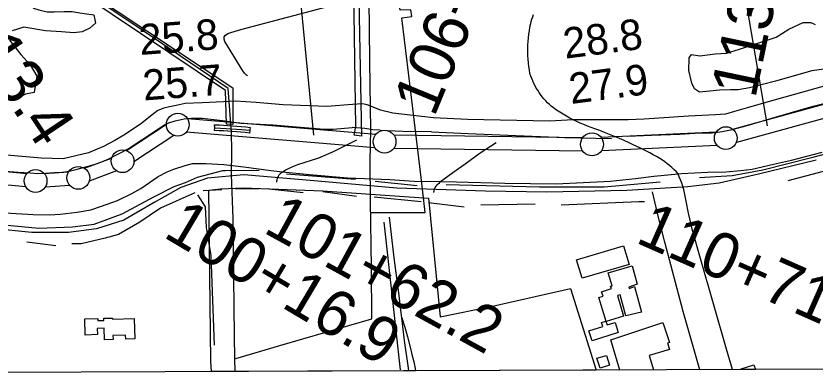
# Model space of a CAD drawing. Extents: x 3392644 to 3430565, y 576657 to 602123.
# Drawn here: x 3398435 to 3400187, y 582044 to 582831 of the extents above; entities that cross this region are included whole.
import ezdxf

# ---------------------------------------------------------------- set-up
doc = ezdxf.new("R2010")
doc.units = 0
for name, color, linetype in [('V-BLDG-OTLN', 7, 'Continuous'), ('V-BRDG-OTLN', 7, 'Continuous'), ('V-CHAN-DOCK', 7, 'Continuous'), ('V-FLOD-BASE', 7, 'Continuous'), ('V-GRID-FRAM', 7, 'Continuous'), ('V-LEVE-TOET', 7, 'Continuous'), ('V-RAIL-TRAK', 7, 'Continuous'), ('V-RIVR-RANG', 7, 'Continuous'), ('V-ROAD-CNTR', 7, 'Continuous'), ('V-SITE-OTLN', 7, 'Continuous'), ('V-SITE-VEGE', 7, 'Continuous'), ('V-SURV-IDEN', 7, 'Continuous'), ('V-SURV-LINE', 7, 'Continuous'), ('V-TOPO-MAJR', 7, 'Continuous'), ('V-TOPO-SHOR', 7, 'Continuous'), ('V-UTIL-LINE', 7, 'Continuous'), ('V-WETL-SWMP', 7, 'Continuous')]:
    doc.layers.add(name, color=color, linetype=linetype)

msp = doc.modelspace()

# ---------------------------------------------------------------- linework, layer by layer
at = {"layer": 'V-BLDG-OTLN'}
for p, q in [((3399739.4, 582121.7), (3399853.2, 582159.3)), ((3399853.2, 582159.3), (3399867.6, 582115.6)), ((3399759, 582055.2), (3399739.4, 582121.7)), ((3399867.6, 582115.6), (3399863.1, 582114.1)), ((3399863.1, 582114.1), (3399868, 582100.4)), ((3399868, 582100.4), (3399823.3, 582087.1)), ((3399823.3, 582087.1), (3399832.8, 582055.4)), ((3400024.7, 582058), (3400052.8, 582066.9)), ((3400052.8, 582066.9), (3400056, 582056.2)), ((3399832.8, 582055.4), (3399759, 582055.2)), ((3400025.3, 582056.1), (3400024.7, 582058)), ((3400056, 582056.2), (3400025.3, 582056.1))]:
    msp.add_line(p, q, dxfattribs=at)
for points in [[(3399779.1, 582286.8), (3399675.9, 582256.3), (3399663.9, 582296.9), (3399766.6, 582327.3)], [(3399766.5, 582173.4), (3399729.2, 582161.7), (3399712.6, 582214.4), (3399721.9, 582217.3), (3399718.9, 582226.8), (3399740.5, 582233.6), (3399738.7, 582239), (3399742.1, 582240), (3399733.2, 582268.4), (3399785.7, 582283.3), (3399797.1, 582243.6), (3399778.3, 582237), (3399779.3, 582234), (3399790.8, 582238.1), (3399806.1, 582182.4), (3399772.3, 582174.2), (3399759.4, 582220.1), (3399753.4, 582218.4)], [(3398585.8, 582167.3), (3398614.1, 582168.3), (3398614.3, 582163.5), (3398627.5, 582163.9), (3398627.4, 582168.6), (3398646, 582169.2), (3398646.1, 582166.6), (3398693.8, 582168.1), (3398695.1, 582123.6), (3398675.3, 582123), (3398675, 582131.8), (3398647.3, 582131), (3398647.6, 582122.1), (3398629.1, 582121.5), (3398628.1, 582147.2), (3398612.9, 582146.6), (3398613.5, 582132.9), (3398586.7, 582131.3)], [(3399755.5, 582137.3), (3399698.2, 582118.9), (3399691.1, 582140.9), (3399721.4, 582150.6), (3399718.5, 582159.6), (3399728.4, 582162.1), (3399730.8, 582154.2), (3399748.9, 582159.7)], [(3399708.7, 582080.9), (3399729.9, 582087.1), (3399736.3, 582065.7), (3399715.4, 582059.5)]]:
    msp.add_lwpolyline(points, close=True, dxfattribs=at)
at = {"layer": 'V-BRDG-OTLN'}
msp.add_lwpolyline([(3398947, 582574.6), (3398937.4, 582575.5), (3398927.8, 582576.4), (3398918.3, 582577.2), (3398908.7, 582577.9), (3398899.1, 582578.6), (3398889.5, 582579.2), (3398879.9, 582579.8), (3398870.3, 582580.3), (3398870.5, 582585.8), (3398870.3, 582592.9), (3398880, 582592.4), (3398889.7, 582591.8), (3398899.5, 582591.1), (3398909.2, 582590.4), (3398918.9, 582589.6), (3398928.7, 582588.8), (3398938.4, 582587.9), (3398948, 582587), (3398948.1, 582586.9), (3398947.5, 582580.6)], close=True, dxfattribs=at)
msp.add_lwpolyline([(3398870.5, 582585.8), (3398895.4, 582584.4), (3398929.7, 582582.7), (3398947.5, 582580.6)], dxfattribs=at)
at = {"layer": 'V-CHAN-DOCK'}
msp.add_lwpolyline([(3398536.3, 583167.9), (3398504.7, 583164), (3398520, 583026.8), (3398526.8, 583027.6), (3398530.3, 583006.9), (3398520.8, 583004.5), (3398533.1, 582924.5), (3398910, 582673.5), (3398910.3, 582593.5), (3398896.4, 582593.9), (3398894, 582667.5), (3398521.5, 582918.1), (3398511.6, 583003.7), (3398504.1, 583002.9), (3398501.3, 583024), (3398508, 583025.2), (3398490.5, 583162.2), (3398455.2, 583157.9), (3398449.8, 583202), (3398530.5, 583211.9)], close=True, dxfattribs=at)
msp.add_lwpolyline([(3399240.3, 583164.2), (3399248.5, 583103), (3399242.2, 583102.2), (3399221.8, 583099.6), (3399217.6, 583133.5), (3399181.5, 583128.9), (3399192.2, 582567.6), (3399176.6, 582569.7), (3399179.6, 582589.2), (3399172.2, 583132.7), (3399148.3, 583130.5), (3399150.6, 583110.2), (3399105.9, 583105), (3399100.8, 583147.8)], dxfattribs=at)
at = {"layer": 'V-FLOD-BASE'}
for p in [(3399233.4, 582581.1), (3399345.7, 582577.5)]:
    msp.add_line(p, (3399299, 582578.1), dxfattribs=at)
for points in [[(3399775.4, 582567.8), (3399828.6, 582570.1), (3399890.1, 582572.5), (3399934.4, 582574.8), (3399961, 582575.4), (3399972.8, 582576.6), (3399982.9, 582577.7), (3400005.3, 582582.5), (3400037.8, 582591.3), (3400089.9, 582606.6), (3400132.4, 582619), (3400182.7, 582633.2), (3400229.4, 582645)], [(3398348.5, 582495.8), (3398438.9, 582488.7), (3398466.1, 582487.5), (3398482.7, 582486.3), (3398499.8, 582486.9), (3398518.7, 582488), (3398536.5, 582489.2), (3398551.2, 582491), (3398569, 582495.1), (3398587.9, 582500.4), (3398613.3, 582507.5), (3398637, 582517.5), (3398680.7, 582540), (3398706.7, 582557.7), (3398720.9, 582566.5), (3398736.9, 582577.2), (3398750.5, 582586), (3398760.5, 582592.5), (3398770, 582597.2), (3398783.6, 582601.4), (3398803.7, 582605.5), (3398819.7, 582607.3), (3398843.3, 582607.3), (3398887.6, 582601.9), (3398927.8, 582596), (3398998.1, 582592.4), (3399049.6, 582588.2), (3399110.4, 582582.9), (3399130, 582582.9), (3399171.9, 582586.4)], [(3399233.4, 582581.1), (3399216.9, 582581.9), (3399199.5, 582584.6), (3399171.9, 582586.4)], [(3399345.7, 582577.5), (3399426.1, 582573.9), (3399513, 582570.3), (3399638.3, 582564.9), (3399740.5, 582562.5)]]:
    msp.add_lwpolyline(points, dxfattribs=at)
at = {"layer": 'V-GRID-FRAM'}
msp.add_lwpolyline([(3396720.3, 600227.7), (3428325.7, 600342.6), (3428399.7, 582159.3), (3396778.5, 582044.3), (3396720.3, 600227.7)], dxfattribs=at)
at = {"layer": 'V-LEVE-TOET'}
for points in [[(3400217.3, 582679.9), (3400078.9, 582641.5), (3400041.1, 582630.3), (3400010.4, 582622.1), (3399990.3, 582616.2), (3399968.4, 582614.4), (3399909.3, 582611.5), (3399812.3, 582605), (3399776.9, 582603.3), (3399737.9, 582603.3), (3399692.9, 582603.9)], [(3399604.9, 582600.4), (3399424.6, 582604), (3399350.1, 582608.2), (3399299.3, 582614.1), (3399260.9, 582618.3), (3399234.3, 582624.8), (3399214.2, 582632.5), (3399204.7, 582636.1), (3399194.7, 582638.4), (3399172.8, 582637.3), (3399116.1, 582632.6), (3399020.3, 582636.7), (3398961.2, 582641.5), (3398916.3, 582644.5), (3398889.7, 582642.7), (3398873.7, 582642.1), (3398843, 582641), (3398805.7, 582639.2), (3398786.2, 582635.1), (3398771.5, 582632.1), (3398759, 582629.2), (3398746, 582623.9), (3398736, 582616.8), (3398707.6, 582594.3), (3398671.5, 582570.1), (3398651.4, 582558.3), (3398626.6, 582545.3), (3398593.5, 582531.2), (3398537.9, 582518.2), (3398490, 582519.4), (3398415, 582525.9)], [(3399692.9, 582603.9), (3399656.8, 582603.6), (3399604.9, 582600.4)], [(3398410.2, 582399.9), (3398472.3, 582395.8), (3398508.4, 582395.7), (3398531.4, 582396.9), (3398568.7, 582401), (3398598.8, 582406.3), (3398622.4, 582414), (3398657.3, 582426.4), (3398688.7, 582442.3), (3398708.2, 582453), (3398746.6, 582479.6), (3398766.1, 582489.6), (3398780.9, 582495.5), (3398805.7, 582503.8), (3398821.7, 582507.9), (3398851.2, 582507.9), (3398890.8, 582505.5), (3398934.6, 582500.2), (3398993.7, 582492.4), (3399018.8, 582489.8), (3399078.2, 582483.5), (3399161.5, 582476.4), (3399254.3, 582472.8), (3399307.5, 582469.2), (3399365.7, 582468.1), (3399400.9, 582467.4), (3399506.7, 582465), (3399619, 582463.2), (3399737.3, 582469), (3399792.8, 582474.9), (3399833, 582480.2), (3399886.4, 582485.4), (3399893.9, 582486.1), (3399951.2, 582489), (3399991.4, 582489.6), (3400024, 582492.5), (3400048.8, 582495.5), (3400096.1, 582506.1), (3400135.1, 582515.5), (3400202.5, 582532.6)]]:
    msp.add_lwpolyline(points, dxfattribs=at)
at = {"layer": 'V-RAIL-TRAK'}
for points in [[(3399295.9, 582053.5), (3399295.2, 582059.2), (3399286.9, 582119.9), (3399280.7, 582169.4), (3399279.2, 582180.9), (3399274.3, 582224.5), (3399264.3, 582301.2), (3399253.4, 582390.2)], [(3399280.7, 582169.4), (3399287.3, 582149.4), (3399293.3, 582127.7), (3399299, 582105.4), (3399303, 582089), (3399307.3, 582073), (3399310.3, 582058.7), (3399311.1, 582053.5)]]:
    msp.add_lwpolyline(points, dxfattribs=at)
at = {"layer": 'V-RIVR-RANG'}
for p, q in [((3399087.9, 582570.1), (3398970.7, 583764.4)), ((3400082.6, 582590.2), (3399897.4, 583674.5))]:
    msp.add_line(p, q, dxfattribs=at)
at = {"layer": 'V-ROAD-CNTR'}
for points in [[(3399703.7, 582584.1), (3399695.7, 582586.9), (3399687.7, 582589.8), (3399679.9, 582593), (3399672.1, 582596.3), (3399664.4, 582599.8), (3399656.8, 582603.6), (3399649.2, 582607.4), (3399641.8, 582611.5), (3399634.4, 582615.7), (3399627.2, 582620.1), (3399620.1, 582624.7), (3399613, 582629.5), (3399608.6, 582633.2), (3399604.3, 582637.1), (3399600.2, 582641.1), (3399596.2, 582645.3), (3399592.3, 582649.6), (3399588.7, 582654.1), (3399585.2, 582658.7), (3399581.8, 582663.4), (3399578.7, 582668.3), (3399575.7, 582673.3), (3399572.9, 582678.3), (3399570.3, 582683.5), (3399567.9, 582688.8), (3399565.6, 582694.1), (3399563.6, 582699.5), (3399561.8, 582705), (3399560.4, 582712.8), (3399559.3, 582720.5), (3399558.4, 582728.4), (3399557.7, 582736.2), (3399557.2, 582744), (3399557, 582751.9), (3399557, 582759.8), (3399557.3, 582767.6), (3399557.7, 582775.5), (3399558.4, 582783.3), (3399559.3, 582791.1), (3399560.5, 582798.9), (3399561.8, 582806.6), (3399563.4, 582814.3), (3399564.6, 582819.4), (3399566, 582824.4), (3399567.7, 582829.4), (3399569.5, 582834.2)], [(3399898.9, 582450.7), (3399896.7, 582457.7), (3399894.4, 582464.7), (3399891.9, 582471.7), (3399889.2, 582478.5), (3399886.4, 582485.4), (3399882, 582490.1), (3399877.3, 582494.6), (3399872.6, 582499), (3399867.7, 582503.3), (3399862.6, 582507.4), (3399857.4, 582511.4), (3399852.1, 582515.2), (3399846.7, 582518.8), (3399839.5, 582523), (3399832.2, 582527.1), (3399824.8, 582531.1), (3399817.4, 582535), (3399809.9, 582538.8), (3399802.3, 582542.5), (3399794.6, 582546.1), (3399786.9, 582549.6), (3399779.2, 582553), (3399768.5, 582557.9), (3399757.8, 582562.6), (3399747.1, 582567.2), (3399736.3, 582571.6), (3399725.4, 582575.9), (3399714.6, 582580.1), (3399703.7, 582584.1)], [(3399098.9, 582520.4), (3399130.7, 582534.1), (3399181.9, 582559.7)], [(3399419.5, 582507.3), (3399452.6, 582531), (3399487.5, 582554.1)], [(3399006.4, 582466.8), (3399006.7, 582469.5), (3399007.2, 582472.2), (3399007.9, 582474.8), (3399008.8, 582477.3), (3399010, 582479.7), (3399011.4, 582482), (3399013, 582484.2), (3399014.7, 582486.2), (3399016.7, 582488.1), (3399018.8, 582489.8), (3399025.3, 582493.4), (3399032, 582496.8), (3399038.8, 582499.9), (3399045.7, 582502.7), (3399052.7, 582505.3), (3399098.9, 582520.4)], [(3400189.5, 582514.8), (3400062.9, 582484.4), (3399976.5, 582465.1), (3399907.8, 582457), (3399774, 582448.6), (3399599.1, 582445.3), (3399464.6, 582446.9), (3399269.5, 582453.5), (3399079.7, 582470.3), (3398934.3, 582483), (3398854.5, 582475.6), (3398796.4, 582454.9), (3398737.9, 582422.6), (3398671.1, 582383.9), (3398611.2, 582365), (3398550.2, 582356.5), (3398469.5, 582356.3), (3398381.7, 582365.6)], [(3399350.6, 582444.1), (3399352.2, 582452.5), (3399354, 582455.4), (3399356.1, 582458.2), (3399358.3, 582460.9), (3399360.6, 582463.4), (3399363.1, 582465.8), (3399365.7, 582468.1), (3399392.8, 582488.4), (3399419.5, 582507.3)], [(3400006.2, 582056.1), (3399992.7, 582101.2), (3399935.5, 582299.9), (3399917.5, 582363.9), (3399908.9, 582402.5), (3399904.9, 582421.9), (3399898.9, 582450.7)], [(3399934.5, 582055.8), (3399897.7, 582183.5), (3399857.7, 582335.6), (3399843.8, 582389.6), (3399830.3, 582445.7)]]:
    msp.add_lwpolyline(points, dxfattribs=at)
at = {"layer": 'V-SITE-OTLN'}
for p, q in [((3398857.9, 582449.4), (3398883.5, 582452.1)), ((3398862.3, 582074.7), (3398857.9, 582449.4)), ((3398883.5, 582452.1), (3398932.9, 582454.8)), ((3398932.9, 582454.8), (3399106.9, 582447.9)), ((3399106.9, 582447.9), (3399339.3, 582432)), ((3399339.3, 582432), (3399364.8, 582171.7)), ((3399479.6, 582195.4), (3399650.4, 582233.9)), ((3399650.4, 582233.9), (3399706.7, 582055)), ((3399364.8, 582171.7), (3399479.6, 582195.4)), ((3398863.4, 582051.9), (3398862.3, 582074.7)), ((3399706.7, 582055), (3398863.4, 582051.9))]:
    msp.add_line(p, q, dxfattribs=at)
at = {"layer": 'V-SITE-VEGE'}
for points in [[(3398416.5, 582902), (3398436, 582889.5), (3398453.7, 582871.6), (3398464.3, 582858.3), (3398473.2, 582848.5), (3398484.7, 582844.9), (3398503.4, 582840.4), (3398518.5, 582840.4), (3398540.7, 582841.2), (3398557.6, 582841.2), (3398570, 582838.5), (3398584.2, 582836.7), (3398605.4, 582833.8), (3398609.2, 582815.1), (3398596.8, 582804.7), (3398580.2, 582796.4), (3398561.5, 582794.4), (3398534.5, 582796.4), (3398499.3, 582798.5), (3398451.6, 582806.8), (3398426.7, 582798.5)], [(3398420.5, 582777.8), (3398445.4, 582746.6), (3398466.1, 582723.8), (3398480.6, 582698.9), (3398474.4, 582663.6), (3398455.7, 582659.5), (3398430.8, 582647)]]:
    msp.add_lwpolyline(points, dxfattribs=at)
at = {"layer": 'V-SURV-LINE'}
for points in [[(3400006.4, 582583.1), (3400610.2, 582749)], [(3400618.1, 582720), (3400014.4, 582554.2)], [(3398810.8, 582606.2), (3399224.2, 582572.3)], [(3397322.9, 582592.6), (3398459.3, 582486.3)], [(3398676.8, 582536.5), (3398764.7, 582594.4)], [(3398781.2, 582569.4), (3398693.3, 582511.4)], [(3399221.8, 582542.4), (3398808.3, 582576.3)], [(3399263.1, 582570.4), (3399678, 582565.1)], [(3399717.1, 582565.7), (3399970.5, 582577.4)], [(3398456.5, 582456.5), (3397320.1, 582562.7)], [(3399677.6, 582535.1), (3399262.7, 582540.4)], [(3399971.9, 582547.5), (3399718.4, 582535.8)], [(3398584.9, 582497.5), (3398644.4, 582519.9)], [(3398496.6, 582486), (3398550.5, 582489.9)], [(3398655, 582491.9), (3398595.5, 582469.4)], [(3398552.7, 582460), (3398498.7, 582456)]]:
    msp.add_lwpolyline(points, dxfattribs=at)
for centre in [(3398789.6, 582592.9), (3399991.2, 582563.4), (3399242.9, 582555.7), (3399697.8, 582549.8), (3398668.4, 582512.9), (3398571.5, 582476.4), (3398477.7, 582469.6)]:
    msp.add_circle(centre, 25, dxfattribs=at)
at = {"layer": 'V-TOPO-MAJR'}
msp.add_lwpolyline([(3398942.3, 582699.7), (3398940.4, 582701.1), (3398935.9, 582705.9), (3398931.9, 582711.2), (3398892.6, 582774.9), (3398891.2, 582780.4), (3398891.5, 582785.3), (3398894.4, 582789.2), (3398899, 582792.6), (3398906.1, 582794.9), (3398913.3, 582797.2), (3398920.6, 582799.3), (3398927.8, 582801.3), (3399146.5, 582859.4)], dxfattribs=at)
at = {"layer": 'V-TOPO-SHOR'}
for p, q in [((3399027.6, 582485.1), (3399179.3, 582473.4)), ((3399222.3, 582469.4), (3399314.5, 582459.5)), ((3398886.4, 582449.8), (3398845.4, 582447.6)), ((3398968.3, 582452.1), (3398917.1, 582451.9)), ((3398988.8, 582452.2), (3399064.6, 582444.3)), ((3399107.6, 582446.5), (3399181.4, 582436.5)), ((3399220.4, 582434.6), (3399322.9, 582424.7)), ((3399339.3, 582422.7), (3399417.2, 582412.8)), ((3399454, 582417), (3399572.9, 582419.5)), ((3399241.1, 582379.3), (3399277.1, 582055.7)), ((3398522.1, 582327.5), (3398458.5, 582335.5))]:
    msp.add_line(p, q, dxfattribs=at)
for points in [[(3400127.9, 582470.7), (3400387.9, 582539.2), (3400670.4, 582614), (3400760.4, 582634.8)], [(3400479.9, 582596.9), (3400338.6, 582563.6), (3400179, 582520), (3400072.5, 582493), (3400005, 582480.5), (3399933.3, 582476.1)], [(3397859.9, 582427.6), (3398167.4, 582398), (3398401, 582374.2), (3398485.1, 582366.3), (3398558.8, 582368.7), (3398605.9, 582375), (3398667.3, 582397.7), (3398736.8, 582434.9), (3398781.8, 582457.6), (3398806.4, 582465.9), (3398833, 582478.2), (3398888.2, 582492.8), (3398894.4, 582492.8), (3398968.2, 582493.1)], [(3399378.1, 582461.8), (3399583, 582456.4), (3399724.3, 582456.9), (3399847.2, 582467.6)], [(3398827, 582443.4), (3398751.3, 582410.3), (3398706.3, 582379.4), (3398659.3, 582352.6), (3398630.6, 582344.3), (3398577.4, 582331.8), (3398556.9, 582331.8)], [(3398833.1, 582439.3), (3398849.6, 582412.7), (3398851.8, 582367.7), (3398862.3, 582306.2), (3398869.2, 582109.6)], [(3399630.2, 582417.6), (3399800.3, 582424.4), (3399812.6, 582424.4)], [(3398908.1, 582053.3), (3398908.1, 582052.1)]]:
    msp.add_lwpolyline(points, dxfattribs=at)
at = {"layer": 'V-UTIL-LINE'}
for points in [[(3398914.6, 582080.6), (3398913.6, 582129.7), (3398911.2, 582387.3), (3398907.5, 582483.9), (3398908.2, 582533.8), (3398907.6, 582576.8), (3398900.1, 582671.9), (3398693, 582812.3), (3398530.2, 582921.3), (3398517.6, 583005.7), (3398516.8, 583014.4), (3398516, 583016.4), (3398496.2, 583166.2)], [(3398917, 582080.2), (3399013.4, 582108.8), (3399215.1, 582167.6), (3399214.2, 582280.2), (3399212.4, 582426.1), (3399211.5, 582513.1), (3399213.1, 582581.4), (3399211.6, 582679.3), (3399210.5, 582732.7), (3399209, 582868.9), (3399209, 582935.6), (3399163.8, 582935), (3399154.5, 583023.3), (3399143.9, 583109.4)], [(3399212.7, 582400.6), (3399332.2, 582400.6), (3399323.5, 582477.3), (3399304.8, 582628.4), (3399280.6, 582826.8), (3399302.4, 582829.9), (3399300.6, 582844.9), (3399277.5, 582843.6), (3399242.2, 583102.2)], [(3398915.1, 582052.1), (3398914.6, 582080.6)]]:
    msp.add_lwpolyline(points, dxfattribs=at)
at = {"layer": 'V-WETL-SWMP'}
msp.add_lwpolyline([(3400232.9, 582718), (3400180.1, 582710.9), (3400099.8, 582688.3), (3400043, 582674), (3400018.3, 582669.2), (3400001.2, 582669.6), (3399977, 582668.4), (3399955.9, 582666.5), (3399933.3, 582664.5), (3399922.2, 582671.7), (3399917, 582683.6), (3399909.9, 582711.4), (3399910.7, 582739.2), (3399916.2, 582746.4), (3399934.5, 582743.6), (3399967.5, 582747.9), (3399992.5, 582749.9), (3400021.5, 582758.6), (3400054.9, 582769.7), (3400101.4, 582784.4), (3400129.3, 582801.9), (3400160.7, 582817), (3400177.4, 582817), (3400187.3, 582812.6)], dxfattribs=at)

# ---------------------------------------------------------------- texts
at = {"layer": 'V-RIVR-RANG'}
for s, rotation, p in [('25.8', 4.3183, (3398707, 582745.5)), ('28.8', 7.3983, (3399638.9, 582737.3)), ('25.7', 4.3183, (3398714.8, 582645.8)), ('27.9', 7.3983, (3399651.7, 582638.1))]:
    msp.add_text(s, height=67, rotation=rotation, dxfattribs=at).set_placement(p)
at = {"layer": 'V-SURV-IDEN'}
for s, rotation, p in [('113+65.6', 78.1998, (3400055.7, 582648.4)), ('106+17.0', 67.6259, (3399351.6, 582607.5)), ('99+13.4', 303.814, (3398215.4, 582942.1)), ('101+62.2', 331.2656, (3398974.3, 582358)), ('100+16.9', 329.3042, (3398755, 582348.3)), ('110+71.9', 336.1536, (3399790.6, 582335.8))]:
    msp.add_text(s, height=100, rotation=rotation, dxfattribs=at).set_placement(p)

doc.saveas('drawing.dxf')
